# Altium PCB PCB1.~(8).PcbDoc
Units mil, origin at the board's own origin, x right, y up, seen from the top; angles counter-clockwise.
Board outline 3715 x 2925 mil, 2 copper layers (Top Layer, Bottom Layer); 4 components, 38 nets, 176 pads, 0 vias.
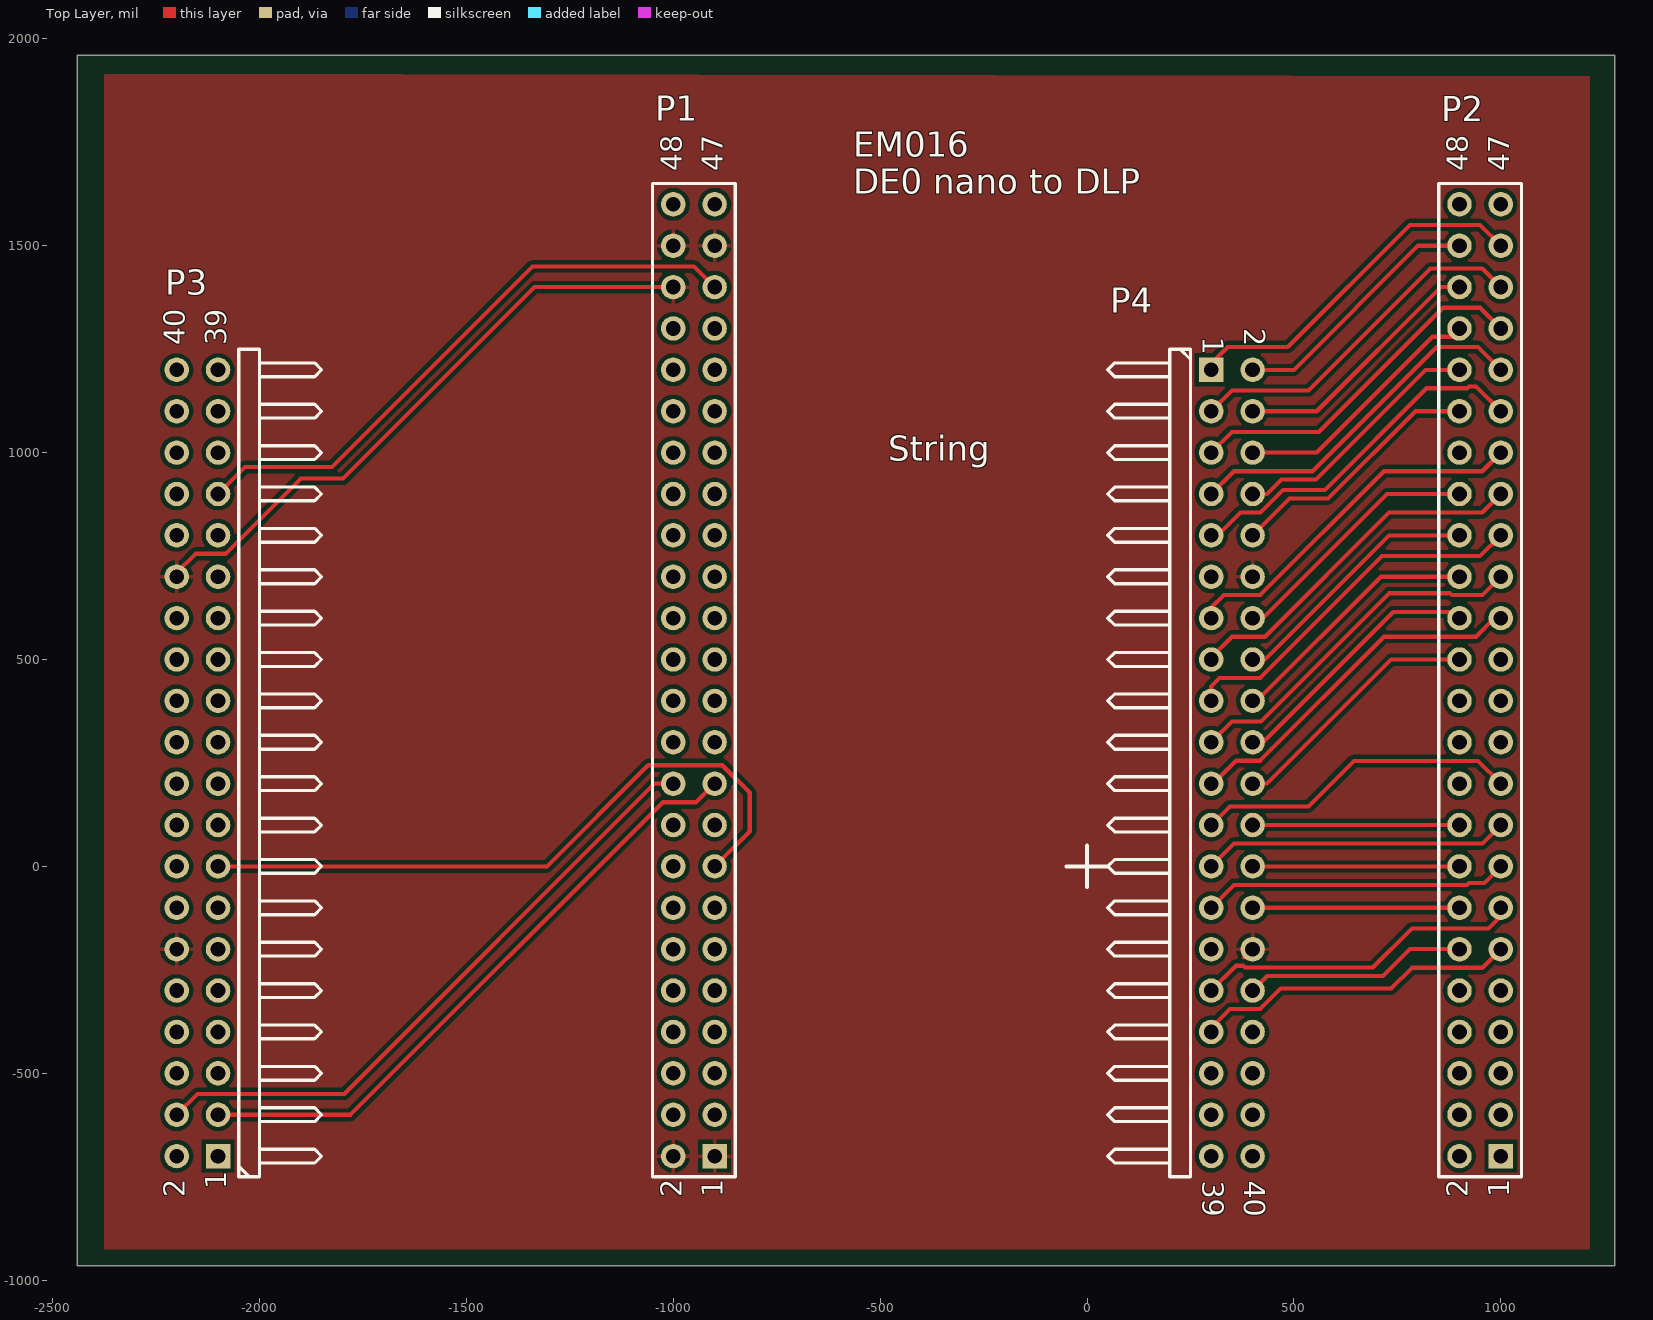
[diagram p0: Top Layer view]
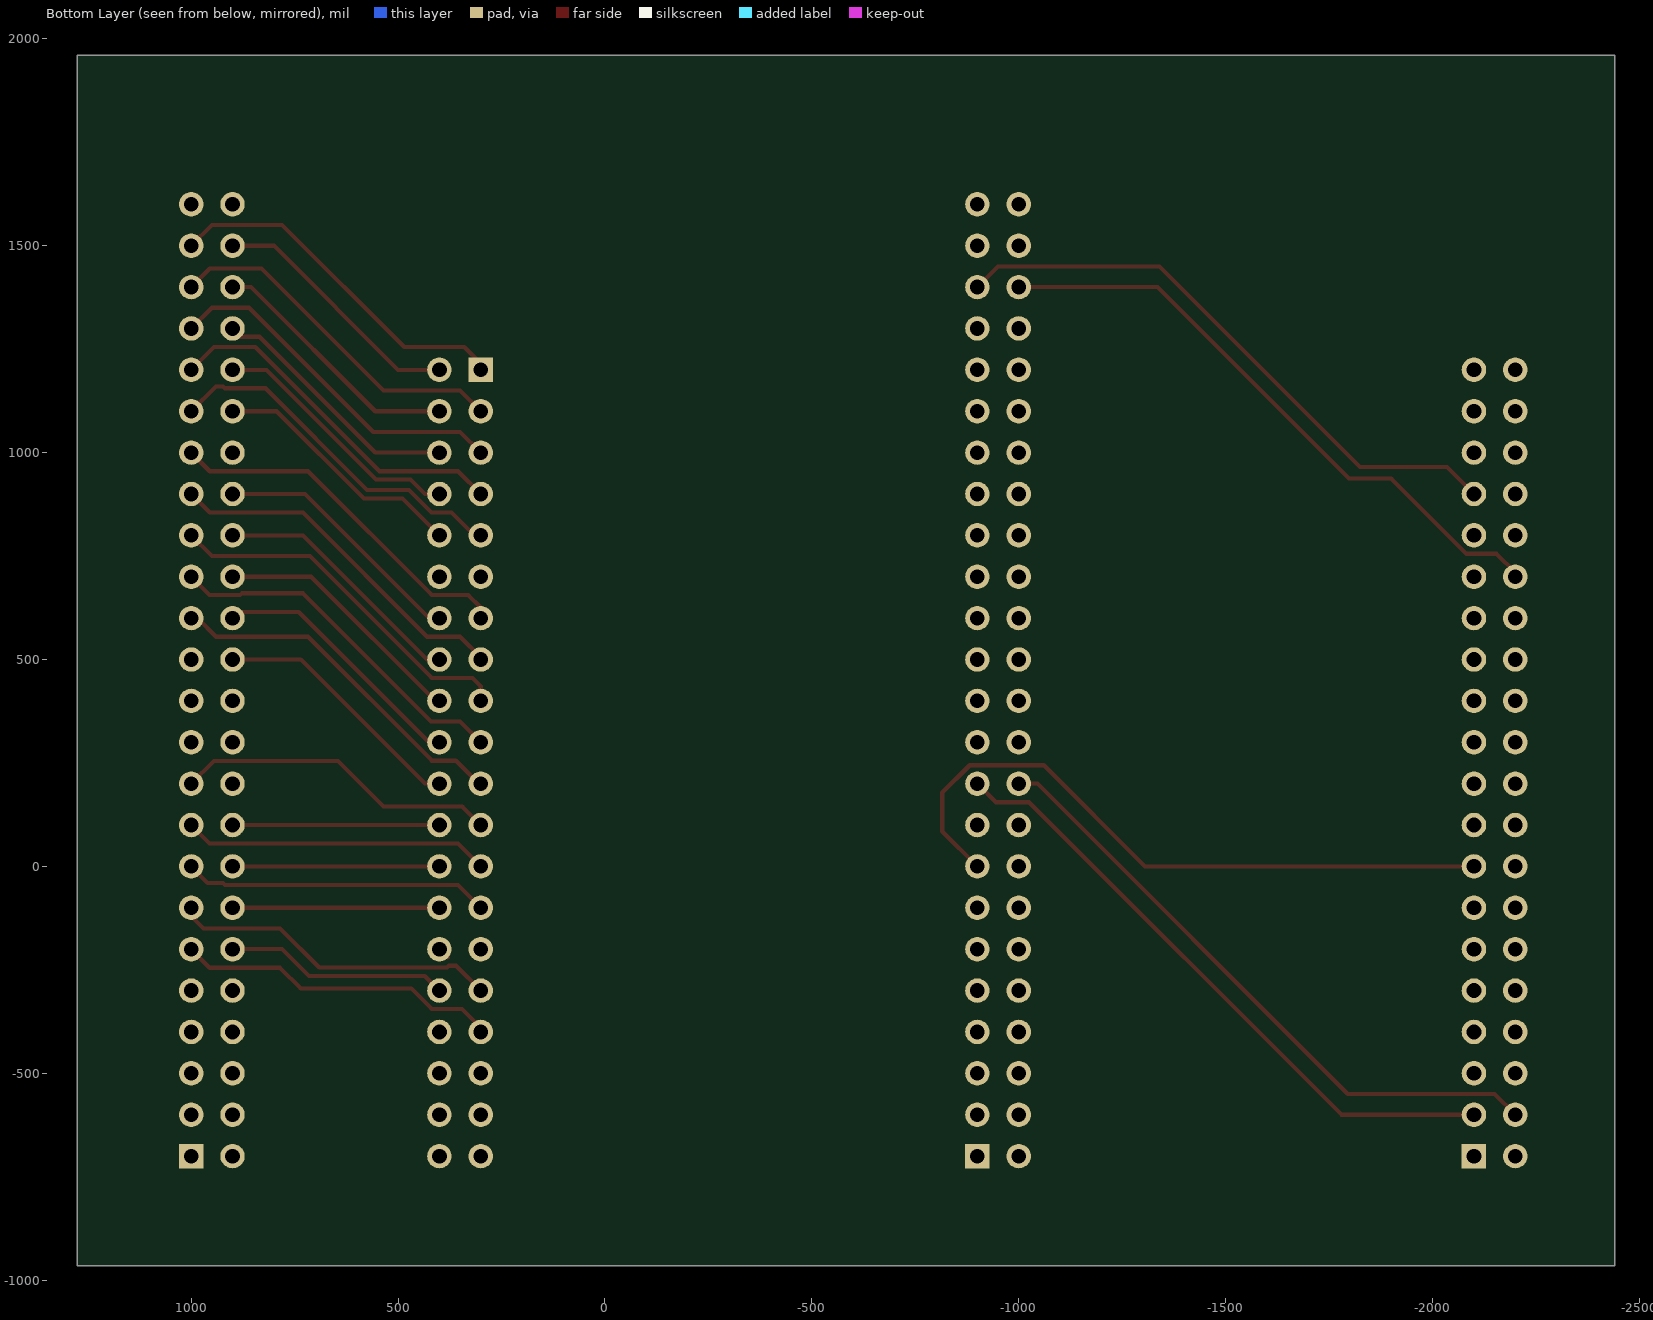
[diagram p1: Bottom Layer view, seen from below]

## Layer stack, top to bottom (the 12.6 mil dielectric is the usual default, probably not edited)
Top Solder: solder mask 0.4, Solder Resist, Dk 3.5
Top Layer: signal copper 1.4
Dielectric 1: dielectric 12.6, FR-4, Dk 4.8
Bottom Layer: signal copper 1.4
Bottom Solder: solder mask 0.4, Solder Resist, Dk 3.5

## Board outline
-2440,-965 1275,-965 1275,1960 -2440,1960

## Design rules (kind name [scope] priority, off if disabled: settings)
Clearance [All] p1: gap=10
PolygonConnect [All] p1: connectstyle=Relief reliefconductorwidth=10 reliefentries=4 polygonreliefangle="90 Angle" airgapwidth=10
RoomDefinition Sheet1 [InComponentClass('Sheet1')] p1 off: confinementstyle=ConfineIn formatcopy=TRUE lockcomponents=FALSE outline 3575,-1835 4940,-1835 4940,860 3575,860
RoutingVias [All] p1: holewidth=28 width=50 viastyle="Through Hole" minholewidth=28 minwidth=50 maxholewidth=28 maxwidth=50
SolderMaskExpansion [All] p1: expansion=4
Width [All] p1: maxlimit=10 minlimit=10 preferedwidth=10
30 further rules are at their usual default settings.

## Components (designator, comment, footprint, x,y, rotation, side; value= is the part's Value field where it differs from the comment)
P1 "Header 24X2" HDR2X24 -900,-700 r90 top
P2 "Header 24X2" HDR2X24 1000,-700 r90 top
P3 "Header 20X2H" HDR2X20H -2100,-700 r90 top
P4 "Header 20X2H" HDR2X20H 300,1200 r270 top

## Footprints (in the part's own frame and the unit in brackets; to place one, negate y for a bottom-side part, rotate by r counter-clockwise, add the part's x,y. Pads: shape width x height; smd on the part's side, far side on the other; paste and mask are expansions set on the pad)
HDR2X20H [mm] "Connector; Header; 20x2 Position; Right Angle"
  rect 1.5x1.5 hole 0.9: 1(0,0)
  round 1.5 hole 0.9: 2(0,2.54) 3(2.54,0) 4(2.54,2.54) 5(5.08,0) 6(5.08,2.54) 7(7.62,0) 8(7.62,2.54) 9(10.16,0) 10(10.16,2.54) 11(12.7,0) 12(12.7,2.54) 13(15.24,0) 14(15.24,2.54) 15(17.78,0) 16(17.78,2.54) 17(20.32,0) 18(20.32,2.54) 19(22.86,0) 20(22.86,2.54) 21(25.4,0) 22(25.4,2.54) 23(27.94,0) 24(27.94,2.54) 25(30.48,0) 26(30.48,2.54) 27(33.02,0) 28(33.02,2.54) 29(35.56,0) 30(35.56,2.54) 31(38.1,0) 32(38.1,2.54) 33(40.64,0) 34(40.64,2.54) 35(43.18,0) 36(43.18,2.54) 37(45.72,0) 38(45.72,2.54) 39(48.26,0) 40(48.26,2.54)
  silkscreen extent -1.27,-6.35 49.53,-1.27
HDR2X24 [mm] "Connector; Header; 24x2 Position"
  rect 1.5x1.5 hole 0.9: 1(0,0)
  round 1.5 hole 0.9: 2(0,2.54) 3(2.54,0) 4(2.54,2.54) 5(5.08,0) 6(5.08,2.54) 7(7.62,0) 8(7.62,2.54) 9(10.16,0) 10(10.16,2.54) 11(12.7,0) 12(12.7,2.54) 13(15.24,0) 14(15.24,2.54) 15(17.78,0) 16(17.78,2.54) 17(20.32,0) 18(20.32,2.54) 19(22.86,0) 20(22.86,2.54) 21(25.4,0) 22(25.4,2.54) 23(27.94,0) 24(27.94,2.54) 25(30.48,0) 26(30.48,2.54) 27(33.02,0) 28(33.02,2.54) 29(35.56,0) 30(35.56,2.54) 31(38.1,0) 32(38.1,2.54) 33(40.64,0) 34(40.64,2.54) 35(43.18,0) 36(43.18,2.54) 37(45.72,0) 38(45.72,2.54) 39(48.26,0) 40(48.26,2.54) 41(50.8,0) 42(50.8,2.54) 43(53.34,0) 44(53.34,2.54) 45(55.88,0) 46(55.88,2.54) 47(58.42,0) 48(58.42,2.54)
  silkscreen extent -1.27,-1.27 59.69,3.81

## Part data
P1 P2: "Header, 24-Pin, Dual row"
P3 P4: "Header, 20-Pin, Dual row, Right Angle"

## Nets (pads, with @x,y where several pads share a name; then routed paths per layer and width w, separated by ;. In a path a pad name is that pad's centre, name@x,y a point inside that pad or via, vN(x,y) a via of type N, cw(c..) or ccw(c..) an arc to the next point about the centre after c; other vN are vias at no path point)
3.3V: P4.29
5V: P4.11
DATA0: P2.45 P4.1 | length 874.5
  Top Layer w10: P4.1 300,1215 340,1255 485,1255 780,1550 950,1550 P2.45
DATA1: P2.46 P4.2 | length 624.3
  Top Layer w10: P4.2 500,1200 800,1500 P2.46
DATA2: P2.43 P4.3 | length 861.5
  Top Layer w10: P4.3 350,1150 535,1150 830,1445 955,1445 P2.43
DATA3: P2.44 P4.4 | length 624.3
  Top Layer w10: P4.4 555,1100 855,1400 P2.44
DATA4: P2.41 P4.5 | length 865.7
  Top Layer w10: P4.5 350,1050 560,1050 860,1350 950,1350 P2.41
DATA5: P2.42 P4.6 | length 624.3
  Top Layer w10: P4.6 555,1000 835,1280 880,1280 P2.42
DATA6: P2.39 P4.7 | length 869.8
  Top Layer w10: P4.7 355,955 545,955 845,1255 945,1255 P2.39
DATA7: P2.40 P4.8 | length 624.3
  Top Layer w10: P4.8 435,900 470,935 553.28,935 818.28,1200 P2.40
DATA8: P2.37 P4.9 | length 874
  Top Layer w10: P4.9 315,800 370.47,855.47 418.76,855.47 473.28,910 575,910 820.47,1155.47 918.44,1155.47 922.97,1160 940,1160 P2.37
DATA9: P2.38 P4.10 | length 624.3
  Top Layer w10: P4.10 489.22,889.22 582.5,889.22 793.28,1100 P2.38
DATA10: P2.36
DATA11: P2.34 P4.14 | length 624.3
  Top Layer w10: P4.14 425,600 725,900 P2.34
DATA12: P2.35 P4.13 | length 880.3
  Top Layer w10: P4.13 300,625 330.47,655.47 418.44,655.47 717.97,955 955,955 P2.35
DATA13: P2.33 P4.15 | length 868.6
  Top Layer w10: P4.15 300,505 350,555 430,555 730,855 955,855 P2.33
DATA14: P2.31 P4.17 | length 886.2
  Top Layer w10: P4.17 300,435 320.47,455.47 418.44,455.47 712.97,750 950,750 P2.31
DATA15: P2.32 P4.16 | length 624.3
  Top Layer w10: P4.16 430,500 730,800 P2.32
DATA16: P2.15 P4.27 | length 741.4
  Top Layer w10: P4.27 355.47,-44.53 918.44,-44.53 922.97,-40 960,-40 P2.15
DATA17: P2.16 P4.26 | length 500
  Top Layer w10: P4.26 P2.16
DATA18: P2.11 P4.33 | length 788.7
  Top Layer w10: P4.33 300,-390 345.47,-344.53 418.44,-344.53 467.97,-295 735,-295 785,-245 955,-245 P2.11
DATA19: P2.12 P4.32 | length 541.4
  Top Layer w10: P4.32 435.47,-264.53 715.47,-264.53 780,-200 P2.12
DATA20: P2.17 P4.25 | length 741.4
  Top Layer w10: P4.25 355.47,55.47 955.47,55.47 P2.17
DATA21: P2.14 P4.28 | length 500
  Top Layer w10: P4.28 P2.14
DATA22: P2.13 P4.31 | length 798.3
  Top Layer w10: P4.31 360,-240 377.03,-240 381.56,-244.53 690.47,-244.53 785,-150 970,-150 1000,-120 P2.13
DATA23: P2.19 P4.23 | length 787
  Top Layer w10: P4.23 345,145 535,145 645,255 945,255 P2.19
DATAEN: P2.30 P4.18 | length 624.3
  Top Layer w10: P4.18 410,400 710,700 P2.30
EXT_SCL: P1.19 P3.3 | length 1531.4
  Top Layer w10: P3.3 -1780,-600 -1025,155 -945,155 P1.19
EXT_SDA: P1.20 P3.4 | length 1531.4
  Top Layer w10: P3.4 -2150,-550 -1795,-550 -1045,200 P1.20
GND: P1.1 P1.2 P1.44 P1.45 P1.46 P3.12 P3.30 P4.12 P4.30 | length 1524.1
  Top Layer w10: P3.30 -2200,710 -2154.53,755.47 -2081.56,755.47 -1900,937.03 -1797.97,937.03 -1335,1400 P1.44 ; P4.30@380,-220 P4.30
GPIO5: P2.18 P4.24 | length 500
  Top Layer w10: P4.24 P2.18
GPIO_INIT_DONE: P2.26 P4.22 | length 624.3
  Top Layer w10: P4.22 435,200 735,500 P2.26
HOST_PRESENTZ: P1.43 P3.33 | length 1448.5
  Top Layer w10: P3.33 -2035,965 -1825,965 -1340,1450 -950,1450 P1.43
HSYNC: P2.29 P4.19 | length 869.4
  Top Layer w10: P4.19 350,350 420,350 730,660 877.03,660 881.56,655.47 955.47,655.47 P2.29
PCLK: P2.28 P4.20 | length 636.7
  Top Layer w10: P4.20 425,300 740,615 885,615 P2.28
PROJ_ON_EXT: P1.15 P3.15 | length 1627
  Top Layer w10: P3.15 -1305,0 -1060.47,244.53 -881.56,244.53 -815,177.97 -815,85 P1.15
VINTF: P1.3
VSYNC: P2.27 P4.21 | length 865.7
  Top Layer w10: P4.21 305,200 360.47,255.47 418.44,255.47 717.97,555 940,555 985,600 P2.27
pads on no net: P1.4 P1.5 P1.6 P1.7 P1.8 P1.9 P1.10 P1.11 P1.12 P1.13 P1.14 P1.16 P1.17 P1.18 P1.21 P1.22 P1.23 P1.24 P1.25 P1.26 P1.27 P1.28 P1.29 P1.30 P1.31 P1.32 P1.33 P1.34 P1.35 P1.36 P1.37 P1.38 P1.39 P1.40 P1.41 P1.42 P1.47 P1.48 P2.1 P2.2 P2.3 P2.4 P2.5 P2.6 P2.7 P2.8 P2.9 P2.10 P2.20 P2.21 P2.22 P2.23 P2.24 P2.25 P2.47 P2.48 P3.1 P3.2 P3.5 P3.6 P3.7 P3.8 P3.9 P3.10 P3.11 P3.13 P3.14 P3.16 P3.17 P3.18 P3.19 P3.20 P3.21 P3.22 P3.23 P3.24 P3.25 P3.26 P3.27 P3.28 P3.29 P3.31 P3.32 P3.34 P3.35 P3.36 P3.37 P3.38 P3.39 P3.40 P4.34 P4.35 P4.36 P4.37 P4.38 P4.39 P4.40

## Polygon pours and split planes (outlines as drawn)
GND on Top Layer "GND top layer" (solid, pour order 0): -2375,1915 -2375,-925 1210,-925 1215,-925 1215,1910

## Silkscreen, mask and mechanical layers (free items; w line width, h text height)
Top Overlay:
  lines w10: -50,0 50,0 ; 0,-50 0,50
  text "EM016 / DE0 nano to DLP" at -565,1625 h60
  text "String" at -480,980 h60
